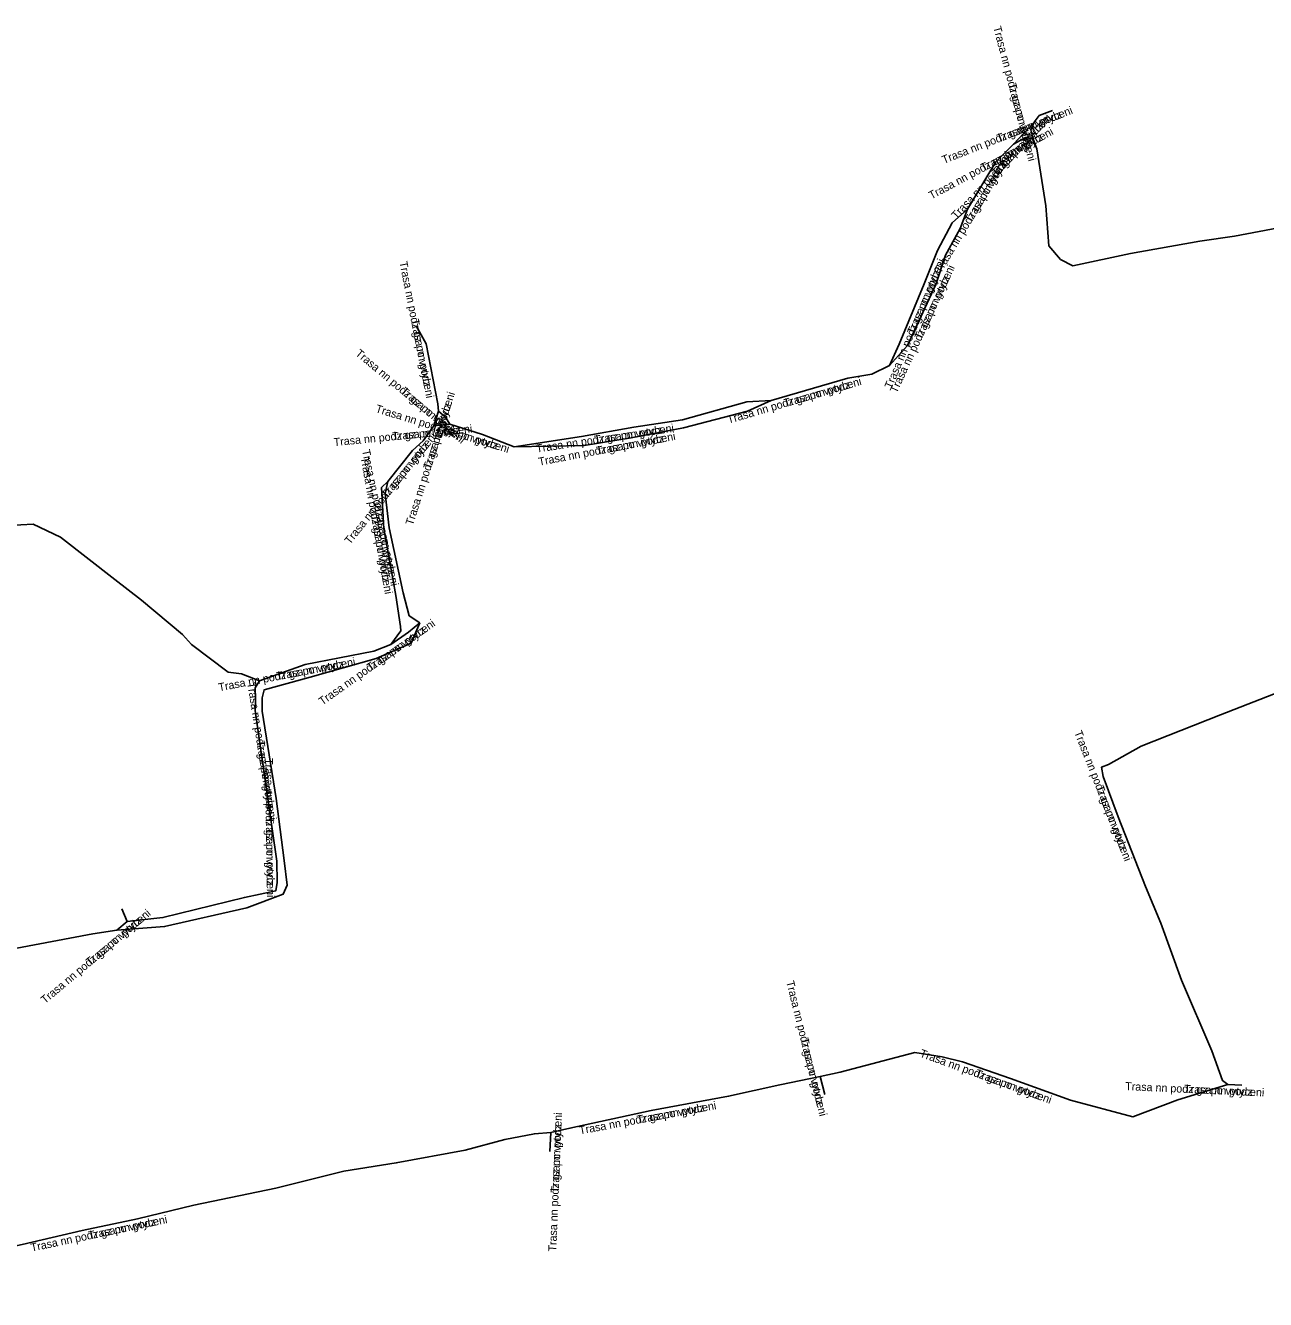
# Model space of a CAD drawing. Extents: x -876384 to -875659, y -1020218 to -1019588.
# Drawn here: x -875956.5 to -875879, y -1020004.6 to -1019925 of the extents above; entities that cross this region are included whole.
import ezdxf

# ---------------------------------------------------------------- set-up
doc = ezdxf.new("R2010")
doc.units = 0
doc.layers.add('Popiskový text - Ostatní atributy Trasy', color=7, linetype='Continuous')
doc.layers.add('Spojnice NN', color=7, linetype='Continuous')

msp = doc.modelspace()

# ---------------------------------------------------------------- linework, layer by layer
at = {"layer": 'Spojnice NN'}
for points in [[(-875893.44, -1019931.07), (-875894.73, -1019932.44)], [(-875893.44, -1019931.07), (-875894.73, -1019932.44)], [(-875893.49, -1019932.13), (-875893.64, -1019931.56), (-875893.44, -1019931.07)], [(-875893.49, -1019932.13), (-875893.64, -1019931.56), (-875893.44, -1019931.07)], [(-875892.3, -1019930.34), (-875893.12, -1019930.66), (-875893.44, -1019931.07)], [(-875892.3, -1019930.34), (-875893.12, -1019930.66), (-875893.44, -1019931.07)], [(-875894.73, -1019932.44), (-875895.83, -1019933.56), (-875897.61, -1019936.52)], [(-875894.73, -1019932.44), (-875895.83, -1019933.56), (-875897.61, -1019936.52)], [(-875894.73, -1019932.44), (-875893.98, -1019932.04), (-875893.49, -1019932.13)], [(-875894.73, -1019932.44), (-875893.98, -1019932.04), (-875893.49, -1019932.13)], [(-875893.49, -1019932.13), (-875893.26, -1019932.75), (-875892.7, -1019936.31), (-875892.51, -1019938.8), (-875891.8, -1019939.65), (-875891.01, -1019940.05), (-875887.42, -1019939.29), (-875883.09, -1019938.51), (-875880.92, -1019938.2), (-875877.07, -1019937.47)], [(-875893.49, -1019932.13), (-875893.26, -1019932.75), (-875892.7, -1019936.31), (-875892.51, -1019938.8), (-875891.8, -1019939.65), (-875891.01, -1019940.05), (-875887.42, -1019939.29), (-875883.09, -1019938.51), (-875880.92, -1019938.2), (-875877.07, -1019937.47)], [(-875902.48, -1019946.27), (-875901.35, -1019945.03), (-875899.59, -1019941.21), (-875898.98, -1019939.39), (-875898.06, -1019937.71), (-875897.61, -1019936.52)], [(-875897.61, -1019936.52), (-875898.55, -1019937.37), (-875899.47, -1019939.1), (-875900.3, -1019941.18), (-875901.87, -1019944.94), (-875902.48, -1019946.27)], [(-875902.48, -1019946.27), (-875901.35, -1019945.03), (-875899.59, -1019941.21), (-875898.98, -1019939.39), (-875898.06, -1019937.71), (-875897.61, -1019936.52)], [(-875897.61, -1019936.52), (-875898.55, -1019937.37), (-875899.47, -1019939.1), (-875900.3, -1019941.18), (-875901.87, -1019944.94), (-875902.48, -1019946.27)], [(-875930.66, -1019949.14), (-875930.69, -1019948.67), (-875931.43, -1019944.93), (-875932.05, -1019943.79)], [(-875930.66, -1019949.14), (-875930.69, -1019948.67), (-875931.43, -1019944.93), (-875932.05, -1019943.79)], [(-875902.48, -1019946.27), (-875903.58, -1019946.82), (-875905.08, -1019947.06), (-875909.87, -1019948.46)], [(-875902.48, -1019946.27), (-875903.58, -1019946.82), (-875905.08, -1019947.06), (-875909.87, -1019948.46)], [(-875909.87, -1019948.46), (-875911.35, -1019949.12), (-875915.34, -1019950.17), (-875918.61, -1019950.79), (-875921.56, -1019951.27), (-875925.93, -1019951.35)], [(-875909.87, -1019948.46), (-875911.4, -1019948.55), (-875915.42, -1019949.68), (-875918.45, -1019950.14), (-875921.73, -1019950.72), (-875925.93, -1019951.35)], [(-875909.87, -1019948.46), (-875911.35, -1019949.12), (-875915.34, -1019950.17), (-875918.61, -1019950.79), (-875921.56, -1019951.27), (-875925.93, -1019951.35)], [(-875909.87, -1019948.46), (-875911.4, -1019948.55), (-875915.42, -1019949.68), (-875918.45, -1019950.14), (-875921.73, -1019950.72), (-875925.93, -1019951.35)], [(-875930.95, -1019950.05), (-875930.66, -1019949.14)], [(-875930.95, -1019950.05), (-875930.66, -1019949.14)], [(-875929.94, -1019949.95), (-875930.22, -1019949.51), (-875930.66, -1019949.14)], [(-875929.94, -1019949.95), (-875930.22, -1019949.51), (-875930.66, -1019949.14)], [(-875933.83, -1019953.52), (-875932.28, -1019951.59), (-875931.61, -1019950.98), (-875930.95, -1019950.05)], [(-875933.83, -1019953.52), (-875932.28, -1019951.59), (-875931.61, -1019950.98), (-875930.95, -1019950.05)], [(-875929.94, -1019949.95), (-875930.95, -1019950.05)], [(-875929.94, -1019949.95), (-875930.95, -1019950.05)], [(-875925.93, -1019951.35), (-875927.9, -1019950.58), (-875929.94, -1019949.95)], [(-875925.93, -1019951.35), (-875927.9, -1019950.58), (-875929.94, -1019949.95)], [(-875933.63, -1019963.7), (-875933, -1019962.85), (-875933.03, -1019962.59), (-875933.33, -1019960.65), (-875934.07, -1019956.49), (-875934.22, -1019953.9), (-875933.83, -1019953.52)], [(-875933.63, -1019963.7), (-875933, -1019962.85), (-875933.03, -1019962.59), (-875933.33, -1019960.65), (-875934.07, -1019956.49), (-875934.22, -1019953.9), (-875933.83, -1019953.52)], [(-875933.83, -1019953.52), (-875933.99, -1019954.28), (-875933.74, -1019956.42), (-875932.87, -1019960.49), (-875932.48, -1019961.91), (-875931.83, -1019962.35)], [(-875933.83, -1019953.52), (-875933.99, -1019954.28), (-875933.74, -1019956.42), (-875932.87, -1019960.49), (-875932.48, -1019961.91), (-875931.83, -1019962.35)], [(-875981.5, -1019959.54), (-875980.91, -1019959.71), (-875978.98, -1019959.19), (-875974.14, -1019958.44), (-875968.61, -1019957.8), (-875964.04, -1019957.02), (-875959.85, -1019956.4), (-875955.98, -1019956.19), (-875954.28, -1019957), (-875950.88, -1019959.65), (-875949.21, -1019960.94), (-875946.66, -1019963.08), (-875946.09, -1019963.7), (-875943.8, -1019965.43), (-875942.97, -1019965.54), (-875941.85, -1019965.97)], [(-875981.5, -1019959.54), (-875980.91, -1019959.71), (-875978.98, -1019959.19), (-875974.14, -1019958.44), (-875968.61, -1019957.8), (-875964.04, -1019957.02), (-875959.85, -1019956.4), (-875955.98, -1019956.19), (-875954.28, -1019957), (-875950.88, -1019959.65), (-875949.21, -1019960.94), (-875946.66, -1019963.08), (-875946.09, -1019963.7), (-875943.8, -1019965.43), (-875942.97, -1019965.54), (-875941.85, -1019965.97)], [(-875950.75, -1019981.55), (-875947.77, -1019981.33), (-875942.63, -1019980.15), (-875940.36, -1019979.3), (-875940.12, -1019978.75), (-875940.29, -1019977.21), (-875940.81, -1019973.33), (-875941.67, -1019967.88), (-875941.68, -1019967.04), (-875941.54, -1019966.53), (-875938.68, -1019965.75), (-875934.56, -1019964.58), (-875932.37, -1019963.63), (-875931.83, -1019962.35)], [(-875950.75, -1019981.55), (-875947.77, -1019981.33), (-875942.63, -1019980.15), (-875940.36, -1019979.3), (-875940.12, -1019978.75), (-875940.29, -1019977.21), (-875940.81, -1019973.33), (-875941.67, -1019967.88), (-875941.68, -1019967.04), (-875941.54, -1019966.53), (-875938.68, -1019965.75), (-875934.56, -1019964.58), (-875932.37, -1019963.63), (-875931.83, -1019962.35)], [(-875933.63, -1019963.7), (-875932.54, -1019962.93), (-875931.83, -1019962.35)], [(-875933.63, -1019963.7), (-875932.54, -1019962.93), (-875931.83, -1019962.35)], [(-875941.85, -1019965.97), (-875938.99, -1019964.95), (-875934.7, -1019964.13), (-875933.63, -1019963.7)], [(-875941.85, -1019965.97), (-875938.99, -1019964.95), (-875934.7, -1019964.13), (-875933.63, -1019963.7)], [(-875950.44, -1019980.22), (-875950.12, -1019981.02), (-875947.88, -1019980.77), (-875942.78, -1019979.51), (-875940.82, -1019979.09), (-875940.74, -1019978.57), (-875940.76, -1019977.24), (-875941.32, -1019973.35), (-875942.12, -1019967.84), (-875942.09, -1019967.08), (-875942.11, -1019966.41), (-875941.85, -1019965.97)], [(-875950.44, -1019980.22), (-875950.12, -1019981.02), (-875947.88, -1019980.77), (-875942.78, -1019979.51), (-875940.82, -1019979.09), (-875940.74, -1019978.57), (-875940.76, -1019977.24), (-875941.32, -1019973.35), (-875942.12, -1019967.84), (-875942.09, -1019967.08), (-875942.11, -1019966.41), (-875941.85, -1019965.97)], [(-875881.33, -1019991.19), (-875881.67, -1019990.95), (-875882.33, -1019989.09), (-875884.22, -1019984.68), (-875885.52, -1019981.11), (-875886.48, -1019978.82), (-875888.18, -1019974.47), (-875889.12, -1019971.95), (-875889.23, -1019971.38), (-875888.79, -1019971.2), (-875886.76, -1019970.06), (-875881.79, -1019968.1), (-875877.62, -1019966.47), (-875877.21, -1019966.53)], [(-875881.33, -1019991.19), (-875881.67, -1019990.95), (-875882.33, -1019989.09), (-875884.22, -1019984.68), (-875885.52, -1019981.11), (-875886.48, -1019978.82), (-875888.18, -1019974.47), (-875889.12, -1019971.95), (-875889.23, -1019971.38), (-875888.79, -1019971.2), (-875886.76, -1019970.06), (-875881.79, -1019968.1), (-875877.62, -1019966.47), (-875877.21, -1019966.53)], [(-875950.12, -1019981.02), (-875950.75, -1019981.55)], [(-875950.12, -1019981.02), (-875950.75, -1019981.55)], [(-875966.57, -1019984.34), (-875964.09, -1019983.91), (-875961.6, -1019983.42), (-875957.01, -1019982.68), (-875952.25, -1019981.79), (-875950.75, -1019981.55)], [(-875966.57, -1019984.34), (-875964.09, -1019983.91), (-875961.6, -1019983.42), (-875957.01, -1019982.68), (-875952.25, -1019981.79), (-875950.75, -1019981.55)], [(-875906.8, -1019990.69), (-875905.56, -1019990.42), (-875900.9, -1019989.19), (-875899.19, -1019989.46), (-875897.91, -1019989.78), (-875894.92, -1019990.82), (-875891.16, -1019992.18), (-875887.28, -1019993.22), (-875884.46, -1019992.16), (-875881.33, -1019991.19)], [(-875906.8, -1019990.69), (-875905.56, -1019990.42), (-875900.9, -1019989.19), (-875899.19, -1019989.46), (-875897.91, -1019989.78), (-875894.92, -1019990.82), (-875891.16, -1019992.18), (-875887.28, -1019993.22), (-875884.46, -1019992.16), (-875881.33, -1019991.19)], [(-875923.64, -1019994.19), (-875922.44, -1019993.93), (-875917.37, -1019992.83), (-875912.53, -1019991.93), (-875909.33, -1019991.22), (-875906.8, -1019990.69)], [(-875923.64, -1019994.19), (-875922.44, -1019993.93), (-875917.37, -1019992.83), (-875912.53, -1019991.93), (-875909.33, -1019991.22), (-875906.8, -1019990.69)], [(-875906.8, -1019990.69), (-875906.52, -1019991.82)], [(-875906.8, -1019990.69), (-875906.52, -1019991.82)], [(-875880.47, -1019991.23), (-875881.33, -1019991.19)], [(-875880.47, -1019991.23), (-875881.33, -1019991.19)], [(-875975.47, -1020004.63), (-875972.34, -1020004.43), (-875968.36, -1020003.82), (-875965.34, -1020003.23), (-875962.55, -1020002.44), (-875956.68, -1020001.19), (-875952.92, -1020000.31), (-875949.46, -1019999.58), (-875945.94, -1019998.74), (-875940.82, -1019997.67), (-875936.58, -1019996.62), (-875933.3, -1019996.1), (-875928.99, -1019995.29), (-875926.52, -1019994.63), (-875924.66, -1019994.27), (-875923.64, -1019994.19)], [(-875975.47, -1020004.63), (-875972.34, -1020004.43), (-875968.36, -1020003.82), (-875965.34, -1020003.23), (-875962.55, -1020002.44), (-875956.68, -1020001.19), (-875952.92, -1020000.31), (-875949.46, -1019999.58), (-875945.94, -1019998.74), (-875940.82, -1019997.67), (-875936.58, -1019996.62), (-875933.3, -1019996.1), (-875928.99, -1019995.29), (-875926.52, -1019994.63), (-875924.66, -1019994.27), (-875923.64, -1019994.19)], [(-875923.69, -1019995.39), (-875923.64, -1019994.19)], [(-875923.69, -1019995.39), (-875923.64, -1019994.19)]]:
    msp.add_lwpolyline(points, dxfattribs=at)

# ---------------------------------------------------------------- texts
at = {"layer": 'Popiskový text - Ostatní atributy Trasy'}
for s, rotation, p in [('Trasa nn podz gz po vytyceni', 284.74356, (-875896, -1019925.147)), ('Trasa nn podz', 284.74356, (-875895.062, -1019928.711)), ('Trasa nn podz gz po vytyceni', 21.31791, (-875899.081, -1019933.684)), ('Trasa nn podz gz po vytyceni', 46.72266, (-875898.296, -1019937.175)), ('Trasa nn podz', 21.31791, (-875895.648, -1019932.344)), ('Trasa nn podz gz po vytyceni', 28.07249, (-875899.858, -1019935.912)), ('Trasa nn podz', 28.07249, (-875896.607, -1019934.178)), ('Trasa nn podz', 46.72266, (-875895.77, -1019934.492)), ('Trasa nn podz gz po vytyceni', 58.97935, (-875899.28, -1019940.557)), ('Trasa nn podz', 58.97935, (-875897.381, -1019937.399)), ('Trasa nn podz gz po vytyceni', 281.19204, (-875933.104, -1019939.818)), ('Trasa nn podz gz po vytyceni', 67.33687, (-875902.347, -1019947.768)), ('Trasa nn podz gz po vytyceni', 65.26292, (-875902.021, -1019948.04)), ('Trasa nn podz', 67.33687, (-875900.927, -1019944.368)), ('Trasa nn podz', 65.26292, (-875900.479, -1019944.693)), ('Trasa nn podz', 281.19204, (-875932.389, -1019943.433)), ('Trasa nn podz gz po vytyceni', 319.93922, (-875935.888, -1019945.593)), ('Trasa nn podz gz po vytyceni', 16.29235, (-875912.532, -1019949.915)), ('Trasa nn podz', 319.93922, (-875933.068, -1019947.965)), ('Trasa nn podz', 16.29235, (-875908.995, -1019948.881)), ('Trasa nn podz gz po vytyceni', 72.32389, (-875932.26, -1019956.302)), ('Trasa nn podz', 72.32389, (-875931.142, -1019952.791)), ('Trasa nn podz gz po vytyceni', 342.83808, (-875934.63, -1019949.182)), ('Trasa nn podz gz po vytyceni', 5.65442, (-875937.181, -1019951.32)), ('Trasa nn podz', 5.65442, (-875933.514, -1019950.957)), ('Trasa nn podz', 342.83808, (-875931.109, -1019950.269)), ('Trasa nn podz gz po vytyceni', 8.63245, (-875924.517, -1019951.719)), ('Trasa nn podz', 8.63245, (-875920.873, -1019951.166)), ('Trasa nn podz gz po vytyceni', 51.23175, (-875936.186, -1019957.492)), ('Trasa nn podz gz po vytyceni', 10.73598, (-875924.36, -1019952.541)), ('Trasa nn podz', 10.73598, (-875920.739, -1019951.855)), ('Trasa nn podz gz po vytyceni', 282.06591, (-875935.44, -1019951.58)), ('Trasa nn podz', 51.23175, (-875933.878, -1019954.619)), ('Trasa nn podz gz po vytyceni', 280.08653, (-875935.524, -1019952.028)), ('Trasa nn podz', 280.08653, (-875934.878, -1019955.656)), ('Trasa nn podz', 282.06591, (-875934.669, -1019955.183)), ('Trasa nn podz gz po vytyceni', 35.23823, (-875937.916, -1019967.523)), ('Trasa nn podz', 35.23823, (-875934.907, -1019965.397)), ('Trasa nn podz gz po vytyceni', 10.82112, (-875944.359, -1019966.638)), ('Trasa nn podz', 10.82112, (-875940.74, -1019965.947)), ('Trasa nn podz gz po vytyceni', 278.96723, (-875942.608, -1019966.109)), ('Trasa nn podz gz po vytyceni', 291.34579, (-875890.939, -1019969.196)), ('Trasa nn podz', 278.96723, (-875942.034, -1019969.749)), ('Trasa nn podz gz po vytyceni', 270.86153, (-875941.507, -1019970.813)), ('Trasa nn podz', 291.34579, (-875889.598, -1019972.628)), ('Trasa nn podz', 270.86153, (-875941.451, -1019974.497)), ('Trasa nn podz gz po vytyceni', 40.07289, (-875955.245, -1019986.181)), ('Trasa nn podz', 40.07289, (-875952.425, -1019983.809)), ('Trasa nn podz gz po vytyceni', 283.91688, (-875908.934, -1019984.779)), ('Trasa nn podz', 283.91688, (-875908.048, -1019988.356)), ('Trasa nn podz gz po vytyceni', 340.11483, (-875900.626, -1019989.447)), ('Trasa nn podz', 340.11483, (-875897.161, -1019990.7)), ('Trasa nn podz gz po vytyceni', 357.337, (-875887.756, -1019991.542)), ('Trasa nn podz', 357.337, (-875884.075, -1019991.713)), ('Trasa nn podz gz po vytyceni', 10.53386, (-875921.821, -1019994.319)), ('Trasa nn podz', 10.53386, (-875918.198, -1019993.645)), ('Trasa nn podz gz po vytyceni', 87.61406, (-875923.3, -1020001.644)), ('Trasa nn podz', 87.61406, (-875923.146, -1019997.962)), ('Trasa nn podz gz po vytyceni', 11.91369, (-875956.08, -1020001.641)), ('Trasa nn podz', 11.91369, (-875952.474, -1020000.88))]:
    msp.add_text(s, height=0.5, rotation=rotation, dxfattribs=at).set_placement(p)

doc.saveas('drawing.dxf')
